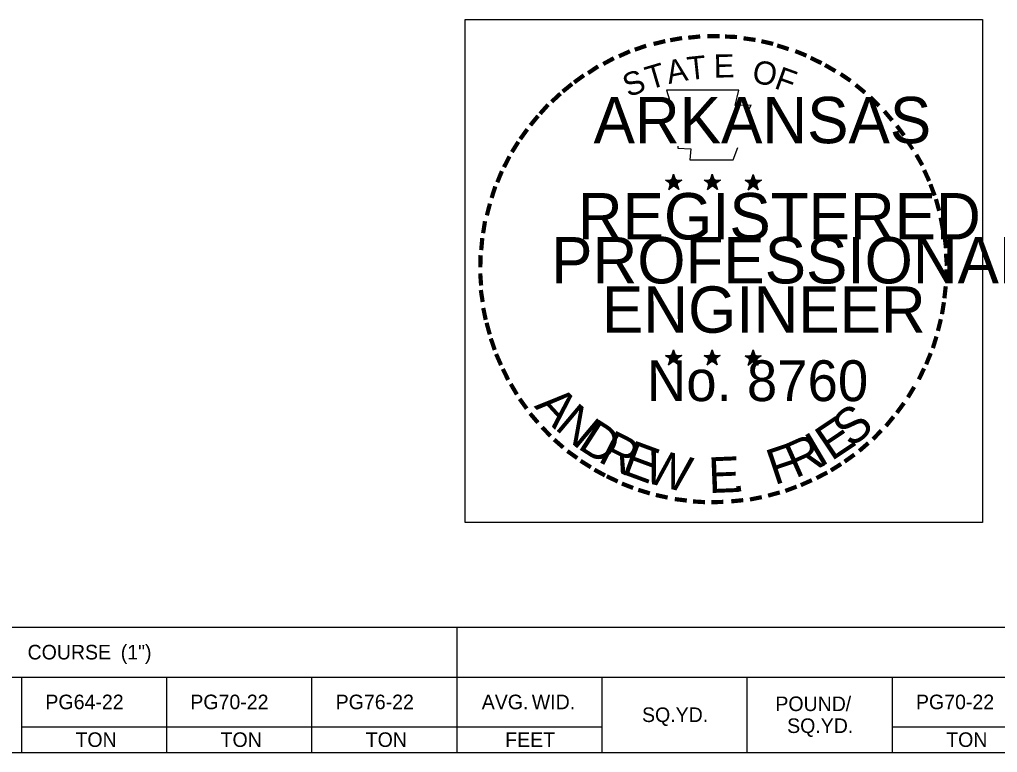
# Model space of a CAD drawing. Extents: x 1226590 to 1228573, y 151304 to 154224.
# Drawn here: x 1227484.8 to 1227748.5, y 152148.3 to 152345.9 of the extents above; entities that cross this region are included whole.
import ezdxf

# ---------------------------------------------------------------- set-up
doc = ezdxf.new("R2010")
doc.units = 0
for name, color, linetype in [('R_Border PE', 7, 'Continuous'), ('R_Border Prem', 7, 'Continuous'), ('R_Dimension', 7, 'Continuous')]:
    doc.layers.add(name, color=color, linetype=linetype)

msp = doc.modelspace()

# ---------------------------------------------------------------- linework, layer by layer
at = {"layer": 'R_Border PE'}
for p, q in [((1227661.2, 152304.28), (1227660.89, 152302.72)), ((1227661.2, 152304.28), (1227660.95, 152302.65)), ((1227661.2, 152304.28), (1227661.14, 152302.72)), ((1227661.2, 152301.97), (1227661.2, 152304.28)), ((1227661.2, 152304.28), (1227661.64, 152302.65)), ((1227661.2, 152304.28), (1227661.52, 152302.72)), ((1227661.2, 152304.28), (1227661.39, 152302.72)), ((1227671.64, 152304.28), (1227671.33, 152302.72)), ((1227671.64, 152304.28), (1227671.39, 152302.65)), ((1227671.64, 152304.28), (1227671.52, 152302.72)), ((1227671.64, 152301.97), (1227671.64, 152304.28)), ((1227671.64, 152304.28), (1227672.08, 152302.65)), ((1227671.64, 152304.28), (1227671.95, 152302.72)), ((1227671.64, 152304.28), (1227671.77, 152302.72)), ((1227659.02, 152302.65), (1227661.2, 152301.97)), ((1227659.02, 152302.65), (1227660.64, 152302.53)), ((1227659.02, 152302.65), (1227660.64, 152302.4)), ((1227659.02, 152302.65), (1227660.58, 152302.28)), ((1227659.02, 152302.65), (1227660.58, 152302.03)), ((1227659.02, 152302.65), (1227660.52, 152301.9)), ((1227659.02, 152302.65), (1227660.52, 152301.78)), ((1227659.89, 152300.09), (1227661.2, 152301.97)), ((1227659.89, 152300.09), (1227660.58, 152301.84)), ((1227659.89, 152300.09), (1227660.64, 152301.65)), ((1227659.89, 152300.09), (1227660.77, 152301.59)), ((1227663.39, 152302.65), (1227661.2, 152301.97)), ((1227662.58, 152300.09), (1227661.2, 152301.97)), ((1227663.39, 152302.65), (1227661.45, 152302.53)), ((1227663.39, 152302.65), (1227661.58, 152302.34)), ((1227663.39, 152302.65), (1227661.58, 152302.22)), ((1227662.58, 152300.09), (1227661.64, 152301.65)), ((1227662.58, 152300.09), (1227661.7, 152301.9)), ((1227662.58, 152300.09), (1227661.83, 152301.97)), ((1227663.39, 152302.65), (1227662.02, 152302.09)), ((1227663.39, 152302.65), (1227662.14, 152302.03)), ((1227663.39, 152302.65), (1227662.2, 152301.97)), ((1227669.45, 152302.65), (1227671.64, 152301.97)), ((1227669.45, 152302.65), (1227671.08, 152302.53)), ((1227669.45, 152302.65), (1227671.08, 152302.4)), ((1227669.45, 152302.65), (1227671.02, 152302.28)), ((1227669.45, 152302.65), (1227670.95, 152302.03)), ((1227669.45, 152302.65), (1227670.95, 152301.9)), ((1227669.45, 152302.65), (1227670.95, 152301.78)), ((1227670.33, 152300.09), (1227671.64, 152301.97)), ((1227670.33, 152300.09), (1227671.02, 152301.84)), ((1227670.33, 152300.09), (1227671.08, 152301.65)), ((1227670.33, 152300.09), (1227671.2, 152301.59)), ((1227673.83, 152302.65), (1227671.64, 152301.97)), ((1227673.02, 152300.09), (1227671.64, 152301.97)), ((1227673.83, 152302.65), (1227671.89, 152302.53)), ((1227673.83, 152302.65), (1227672.02, 152302.34)), ((1227673.83, 152302.65), (1227672.02, 152302.22)), ((1227673.02, 152300.09), (1227672.08, 152301.65)), ((1227673.02, 152300.09), (1227672.14, 152301.9)), ((1227673.02, 152300.09), (1227672.27, 152301.97)), ((1227673.83, 152302.65), (1227672.45, 152302.09)), ((1227673.83, 152302.65), (1227672.58, 152302.03)), ((1227673.83, 152302.65), (1227672.64, 152301.97)), ((1227680.52, 152302.59), (1227682.7, 152301.9)), ((1227680.52, 152302.59), (1227682.14, 152302.4)), ((1227680.52, 152302.59), (1227682.08, 152302.28)), ((1227680.52, 152302.59), (1227682.08, 152302.22)), ((1227680.52, 152302.59), (1227682.02, 152301.97)), ((1227680.52, 152302.59), (1227682.02, 152301.84)), ((1227680.52, 152302.59), (1227682.02, 152301.72)), ((1227681.33, 152300.03), (1227682.7, 152301.9)), ((1227681.33, 152300.03), (1227682.08, 152301.78)), ((1227681.33, 152300.03), (1227682.14, 152301.59)), ((1227681.33, 152300.03), (1227682.27, 152301.53)), ((1227682.7, 152304.15), (1227682.33, 152302.65)), ((1227682.7, 152304.15), (1227682.45, 152302.59)), ((1227682.7, 152304.15), (1227682.58, 152302.59)), ((1227682.7, 152301.9), (1227682.7, 152304.15)), ((1227682.7, 152304.15), (1227683.14, 152302.59)), ((1227682.7, 152304.15), (1227683.02, 152302.59)), ((1227682.7, 152304.15), (1227682.83, 152302.65)), ((1227684.89, 152302.59), (1227682.7, 152301.9)), ((1227684.02, 152300.03), (1227682.7, 152301.9)), ((1227684.89, 152302.59), (1227682.95, 152302.47)), ((1227684.89, 152302.59), (1227683.08, 152302.28)), ((1227684.89, 152302.59), (1227683.08, 152302.15)), ((1227684.02, 152300.03), (1227683.14, 152301.59)), ((1227684.02, 152300.03), (1227683.2, 152301.84)), ((1227684.02, 152300.03), (1227683.33, 152301.84)), ((1227684.89, 152302.59), (1227683.52, 152302.03)), ((1227684.89, 152302.59), (1227683.58, 152301.97)), ((1227684.89, 152302.59), (1227683.7, 152301.9)), ((1227659.89, 152300.09), (1227661.2, 152301.47)), ((1227659.89, 152300.09), (1227660.95, 152301.4)), ((1227659.89, 152300.09), (1227661.27, 152301.28)), ((1227662.58, 152300.09), (1227661.2, 152301.47)), ((1227662.58, 152300.09), (1227661.2, 152301.28)), ((1227662.58, 152300.09), (1227661.45, 152301.4)), ((1227670.33, 152300.09), (1227671.64, 152301.47)), ((1227670.33, 152300.09), (1227671.39, 152301.4)), ((1227670.33, 152300.09), (1227671.7, 152301.28)), ((1227673.02, 152300.09), (1227671.64, 152301.47)), ((1227673.02, 152300.09), (1227671.64, 152301.28)), ((1227673.02, 152300.09), (1227671.89, 152301.4)), ((1227681.33, 152300.03), (1227682.7, 152301.4)), ((1227681.33, 152300.03), (1227682.45, 152301.34)), ((1227681.33, 152300.03), (1227682.77, 152301.22)), ((1227684.02, 152300.03), (1227682.7, 152301.4)), ((1227684.02, 152300.03), (1227682.7, 152301.22)), ((1227684.02, 152300.03), (1227682.95, 152301.34)), ((1227661.2, 152256.9), (1227660.83, 152255.4)), ((1227661.2, 152256.9), (1227660.95, 152255.34)), ((1227661.2, 152256.9), (1227661.08, 152255.34)), ((1227661.2, 152254.65), (1227661.2, 152256.9)), ((1227661.2, 152256.9), (1227661.64, 152255.34)), ((1227661.2, 152256.9), (1227661.52, 152255.34)), ((1227661.2, 152256.9), (1227661.33, 152255.34)), ((1227671.64, 152256.9), (1227671.27, 152255.4)), ((1227671.64, 152256.9), (1227671.39, 152255.34)), ((1227671.64, 152256.9), (1227671.52, 152255.34)), ((1227671.64, 152254.65), (1227671.64, 152256.9)), ((1227671.64, 152256.9), (1227672.02, 152255.34)), ((1227671.64, 152256.9), (1227671.95, 152255.34)), ((1227671.64, 152256.9), (1227671.77, 152255.34)), ((1227682.7, 152256.84), (1227682.33, 152255.28)), ((1227682.7, 152256.84), (1227682.45, 152255.28)), ((1227682.7, 152256.84), (1227682.58, 152255.28)), ((1227682.7, 152254.59), (1227682.7, 152256.84)), ((1227682.7, 152256.84), (1227683.08, 152255.28)), ((1227682.7, 152256.84), (1227683.02, 152255.28)), ((1227682.7, 152256.84), (1227682.83, 152255.28)), ((1227659.02, 152255.34), (1227661.2, 152254.65)), ((1227659.02, 152255.34), (1227660.64, 152255.15)), ((1227659.02, 152255.34), (1227660.58, 152255.03)), ((1227659.02, 152255.34), (1227660.58, 152254.97)), ((1227659.02, 152255.34), (1227660.52, 152254.72)), ((1227659.02, 152255.34), (1227660.52, 152254.59)), ((1227659.02, 152255.34), (1227660.52, 152254.47)), ((1227659.83, 152252.78), (1227661.2, 152254.65)), ((1227659.83, 152252.78), (1227660.58, 152254.53)), ((1227659.83, 152252.78), (1227660.64, 152254.28)), ((1227659.83, 152252.78), (1227660.77, 152254.22)), ((1227659.83, 152252.78), (1227661.2, 152254.15)), ((1227659.83, 152252.78), (1227660.95, 152254.09)), ((1227663.39, 152255.34), (1227661.2, 152254.65)), ((1227662.52, 152252.78), (1227661.2, 152254.65)), ((1227662.52, 152252.78), (1227661.2, 152254.09)), ((1227662.52, 152252.78), (1227661.39, 152254.09)), ((1227663.39, 152255.34), (1227661.45, 152255.22)), ((1227663.39, 152255.34), (1227661.58, 152255.03)), ((1227663.39, 152255.34), (1227661.58, 152254.9)), ((1227662.52, 152252.78), (1227661.64, 152254.59)), ((1227662.52, 152252.78), (1227661.64, 152254.34)), ((1227662.52, 152252.78), (1227661.83, 152254.59)), ((1227663.39, 152255.34), (1227661.95, 152254.78)), ((1227663.39, 152255.34), (1227662.08, 152254.72)), ((1227663.39, 152255.34), (1227662.2, 152254.59)), ((1227669.45, 152255.34), (1227671.64, 152254.65)), ((1227669.45, 152255.34), (1227671.02, 152255.15)), ((1227669.45, 152255.34), (1227671.02, 152255.03)), ((1227669.45, 152255.34), (1227671.02, 152254.97)), ((1227669.45, 152255.34), (1227670.95, 152254.72)), ((1227669.45, 152255.34), (1227670.95, 152254.59)), ((1227669.45, 152255.34), (1227670.95, 152254.47)), ((1227670.27, 152252.78), (1227671.64, 152254.65)), ((1227670.27, 152252.78), (1227671.02, 152254.53)), ((1227670.27, 152252.78), (1227671.08, 152254.28)), ((1227670.27, 152252.78), (1227671.2, 152254.22)), ((1227670.27, 152252.78), (1227671.64, 152254.15)), ((1227670.27, 152252.78), (1227671.39, 152254.09)), ((1227673.77, 152255.34), (1227671.64, 152254.65)), ((1227672.95, 152252.78), (1227671.64, 152254.65)), ((1227672.95, 152252.78), (1227671.64, 152254.09)), ((1227672.95, 152252.78), (1227671.83, 152254.09)), ((1227673.77, 152255.34), (1227671.89, 152255.22)), ((1227673.77, 152255.34), (1227672.02, 152255.03)), ((1227673.77, 152255.34), (1227672.02, 152254.9)), ((1227672.95, 152252.78), (1227672.08, 152254.59)), ((1227672.95, 152252.78), (1227672.08, 152254.34)), ((1227672.95, 152252.78), (1227672.27, 152254.59)), ((1227673.77, 152255.34), (1227672.39, 152254.78)), ((1227673.77, 152255.34), (1227672.52, 152254.72)), ((1227673.77, 152255.34), (1227672.64, 152254.59)), ((1227680.52, 152255.28), (1227682.7, 152254.59)), ((1227680.52, 152255.28), (1227682.08, 152255.09)), ((1227680.52, 152255.28), (1227682.08, 152254.97)), ((1227680.52, 152255.28), (1227682.02, 152254.84)), ((1227680.52, 152255.28), (1227682.02, 152254.65)), ((1227680.52, 152255.28), (1227681.95, 152254.47)), ((1227680.52, 152255.28), (1227681.95, 152254.34)), ((1227681.33, 152252.72), (1227682.7, 152254.59)), ((1227681.33, 152252.72), (1227682.02, 152254.47)), ((1227681.33, 152252.72), (1227682.08, 152254.22)), ((1227681.33, 152252.72), (1227682.27, 152254.15)), ((1227684.83, 152255.28), (1227682.7, 152254.59)), ((1227684.02, 152252.72), (1227682.7, 152254.59)), ((1227684.83, 152255.28), (1227682.95, 152255.15)), ((1227684.83, 152255.28), (1227683.08, 152254.97)), ((1227684.83, 152255.28), (1227683.08, 152254.84)), ((1227684.02, 152252.72), (1227683.08, 152254.22)), ((1227684.02, 152252.72), (1227683.14, 152254.53)), ((1227684.02, 152252.72), (1227683.27, 152254.53)), ((1227684.83, 152255.28), (1227683.45, 152254.72)), ((1227684.83, 152255.28), (1227683.58, 152254.59)), ((1227684.83, 152255.28), (1227683.64, 152254.53)), ((1227659.83, 152252.78), (1227661.2, 152253.97)), ((1227662.52, 152252.78), (1227661.14, 152253.97)), ((1227670.27, 152252.78), (1227671.64, 152253.97)), ((1227672.95, 152252.78), (1227671.58, 152253.97)), ((1227681.33, 152252.72), (1227682.45, 152254.03)), ((1227681.33, 152252.72), (1227682.64, 152254.03)), ((1227681.33, 152252.72), (1227682.7, 152253.9)), ((1227684.02, 152252.72), (1227682.64, 152254.03)), ((1227684.02, 152252.72), (1227682.64, 152253.84)), ((1227684.02, 152252.72), (1227682.89, 152254.03))]:
    msp.add_line(p, q, dxfattribs=at)
for points in [[(1227659.33, 152326.9), (1227660.95, 152321.72)], [(1227681.27, 152321.15), (1227682.14, 152322.9), (1227677.83, 152322.78), (1227678.77, 152326.9), (1227659.33, 152326.9)], [(1227662.39, 152311.78), (1227662.39, 152311.22), (1227665.89, 152311.09), (1227665.58, 152308.15), (1227677.27, 152308.15), (1227678.52, 152311.47)], [(1227661.2, 152304.28), (1227662.58, 152300.09), (1227659.02, 152302.65), (1227663.39, 152302.65), (1227659.89, 152300.09), (1227661.2, 152304.28)], [(1227671.64, 152304.28), (1227673.02, 152300.09), (1227669.45, 152302.65), (1227673.83, 152302.65), (1227670.33, 152300.09), (1227671.64, 152304.28)], [(1227682.7, 152304.15), (1227684.02, 152300.03), (1227680.52, 152302.59), (1227684.89, 152302.59), (1227681.33, 152300.03), (1227682.7, 152304.15)], [(1227661.2, 152256.9), (1227662.52, 152252.78), (1227659.02, 152255.34), (1227663.39, 152255.34), (1227659.83, 152252.78), (1227661.2, 152256.9)], [(1227671.64, 152256.9), (1227672.95, 152252.78), (1227669.45, 152255.34), (1227673.77, 152255.34), (1227670.27, 152252.78), (1227671.64, 152256.9)], [(1227682.7, 152256.84), (1227684.02, 152252.72), (1227680.52, 152255.28), (1227684.83, 152255.28), (1227681.33, 152252.72), (1227682.7, 152256.84)]]:
    msp.add_lwpolyline(points, dxfattribs=at)
for centre, radius in [((1227661.22, 152301.96), 1.08), ((1227661.22, 152301.96), 0.975), ((1227661.22, 152301.96), 0.904), ((1227661.22, 152301.96), 0.83), ((1227661.22, 152301.96), 0.723), ((1227661.22, 152301.96), 0.672), ((1227661.22, 152301.96), 0.619), ((1227661.22, 152301.96), 0.533), ((1227661.22, 152301.96), 0.467), ((1227661.22, 152301.96), 0.388), ((1227661.22, 152301.96), 0.31), ((1227661.22, 152301.96), 0.231), ((1227661.22, 152301.96), 0.185), ((1227661.22, 152301.96), 0.0901), ((1227671.65, 152301.96), 1.08), ((1227671.65, 152301.96), 0.975), ((1227671.65, 152301.96), 0.904), ((1227671.65, 152301.96), 0.83), ((1227671.65, 152301.96), 0.723), ((1227671.65, 152301.96), 0.672), ((1227671.65, 152301.96), 0.619), ((1227671.65, 152301.96), 0.533), ((1227671.65, 152301.96), 0.467), ((1227671.65, 152301.96), 0.388), ((1227671.65, 152301.96), 0.31), ((1227671.65, 152301.96), 0.231), ((1227671.65, 152301.96), 0.185), ((1227671.65, 152301.96), 0.0901), ((1227682.7, 152301.89), 1.08), ((1227682.7, 152301.89), 0.975), ((1227682.7, 152301.89), 0.904), ((1227682.7, 152301.89), 0.83), ((1227682.7, 152301.89), 0.723), ((1227682.7, 152301.89), 0.672), ((1227682.7, 152301.89), 0.619), ((1227682.7, 152301.89), 0.533), ((1227682.7, 152301.89), 0.467), ((1227682.7, 152301.89), 0.388), ((1227682.7, 152301.89), 0.31), ((1227682.7, 152301.89), 0.231), ((1227682.7, 152301.89), 0.185), ((1227682.7, 152301.89), 0.0901), ((1227661.2, 152254.63), 1.08), ((1227661.2, 152254.63), 0.975), ((1227661.2, 152254.63), 0.904), ((1227661.2, 152254.63), 0.83), ((1227661.2, 152254.63), 0.723), ((1227661.2, 152254.63), 0.672), ((1227661.2, 152254.63), 0.619), ((1227661.2, 152254.63), 0.533), ((1227661.2, 152254.63), 0.467), ((1227661.2, 152254.63), 0.388), ((1227661.2, 152254.63), 0.31), ((1227661.2, 152254.63), 0.231), ((1227661.2, 152254.63), 0.185), ((1227661.2, 152254.63), 0.0901), ((1227671.63, 152254.63), 1.08), ((1227671.63, 152254.63), 0.975), ((1227671.63, 152254.63), 0.904), ((1227671.63, 152254.63), 0.83), ((1227671.63, 152254.63), 0.723), ((1227671.63, 152254.63), 0.672), ((1227671.63, 152254.63), 0.619), ((1227671.63, 152254.63), 0.533), ((1227671.63, 152254.63), 0.467), ((1227671.63, 152254.63), 0.388), ((1227671.63, 152254.63), 0.31), ((1227671.63, 152254.63), 0.231), ((1227671.63, 152254.63), 0.185), ((1227671.63, 152254.63), 0.0901), ((1227682.67, 152254.56), 1.08), ((1227682.67, 152254.56), 0.975), ((1227682.67, 152254.56), 0.904), ((1227682.67, 152254.56), 0.83), ((1227682.67, 152254.56), 0.723), ((1227682.67, 152254.56), 0.672), ((1227682.67, 152254.56), 0.619), ((1227682.67, 152254.56), 0.533), ((1227682.67, 152254.56), 0.467), ((1227682.67, 152254.56), 0.388), ((1227682.67, 152254.56), 0.31), ((1227682.67, 152254.56), 0.231), ((1227682.67, 152254.56), 0.185), ((1227682.67, 152254.56), 0.0901)]:
    msp.add_circle(centre, radius, dxfattribs=at)
at = {"layer": 'R_Border Prem'}
msp.add_lwpolyline([(1227604.98, 152345.95), (1227744.48, 152345.95), (1227744.48, 152210.33), (1227604.98, 152210.33)], close=True, dxfattribs=at)
at = {"layer": 'R_Dimension'}
for p, q in [((1226590.27, 152182.03), (1228150.73, 152182.03)), ((1227602.82, 152148.27), (1227602.82, 152182.03)), ((1226898.37, 152168.6), (1228150.73, 152168.6)), ((1227485.41, 152148.27), (1227485.41, 152168.6)), ((1227524.55, 152148.27), (1227524.55, 152168.6)), ((1227563.69, 152148.27), (1227563.69, 152168.6)), ((1227641.96, 152148.27), (1227641.96, 152168.6)), ((1227681.09, 152148.27), (1227681.09, 152168.6)), ((1227720.23, 152148.27), (1227720.23, 152168.6)), ((1227485.41, 152155.17), (1227641.96, 152155.17)), ((1227720.23, 152155.17), (1227837.64, 152155.17)), ((1226590.27, 152148.27), (1228150.73, 152148.27)), ((1227407.14, 152148.27), (1227641.96, 152148.27)), ((1227641.96, 152148.27), (1227876.78, 152148.27))]:
    msp.add_line(p, q, dxfattribs=at)

# ---------------------------------------------------------------- texts
at = {"layer": 'R_Border PE'}
for s, height, rotation, p in [('-', 10, 10.2193, (1227660.39, 152336.47)), ('-', 10, 5.8968, (1227664.95, 152337.15)), ('-', 10, 0.1862, (1227669.77, 152337.59)), ('-', 10, 357.743, (1227674.33, 152337.53)), ('-', 10, 352.1617, (1227678.95, 152337.15)), ('-', 10, 19.1761, (1227651.45, 152333.97)), ('-', 10, 13.6302, (1227656.14, 152335.47)), ('-', 10, 347.2049, (1227683.45, 152336.47)), ('-', 10, 342.3362, (1227687.39, 152335.47)), ('-', 10, 28.7918, (1227643.58, 152330.28)), ('-', 10, 24.3072, (1227647.52, 152332.28)), ('T', 6.25, 6.0228, (1227665.2, 152329.59)), ('E', 6.25, 0.8323, (1227672.08, 152330.28)), ('-', 10, 337.8551, (1227692.02, 152334.09)), ('-', 10, 334.1211, (1227695.95, 152332.4)), ('-', 10, 34.0636, (1227639.83, 152327.97)), ('T', 6.25, 16.4036, (1227654.7, 152326.97)), ('A', 6.25, 11.2132, (1227659.89, 152328.53)), ('O', 6.25, 350.4515, (1227682.14, 152328.97)), ('-', 10, 329.6409, (1227699.58, 152330.65)), ('-', 10, 36.2317, (1227636.2, 152325.53)), ('S', 6.25, 21.594, (1227649.02, 152324.9)), ('F', 6.25, 340.0707, (1227688.08, 152327.53)), ('-', 10, 325.8627, (1227703.58, 152328.4)), ('-', 10, 38.9507, (1227633.27, 152323.15)), ('-', 10, 320.5297, (1227707.39, 152325.72)), ('-', 10, 42.9622, (1227630.52, 152320.53)), ('-', 10, 315.5786, (1227711.14, 152322.65)), ('-', 10, 48.423, (1227627.7, 152317.53)), ('-', 10, 50.6142, (1227625.2, 152314.53)), ('-', 10, 309.8797, (1227714.7, 152319.22)), ('-', 10, 306.6522, (1227717.95, 152315.47)), ('-', 10, 54.2325, (1227622.64, 152310.97)), ('-', 10, 58.0706, (1227620.58, 152307.65)), ('-', 8.75, 303.6753, (1227721.02, 152311.9)), ('-', 10, 299.6684, (1227723.02, 152308.09)), ('-', 10, 62.8713, (1227618.64, 152303.84)), ('-', 10, 67.7743, (1227617.02, 152300.03)), ('-', 10, 294.6628, (1227725.02, 152304.28)), ('-', 10, 290.5728, (1227726.64, 152300.72)), ('-', 10, 72.3945, (1227615.64, 152296.09)), ('-', 10, 75.461, (1227614.45, 152291.59)), ('-', 10, 285.1233, (1227728.08, 152297.09)), ('-', 10, 81.2013, (1227613.58, 152287.15)), ('-', 10, 280.5493, (1227729.33, 152292.4)), ('-', 10, 85.1863, (1227613.14, 152282.84)), ('-', 10, 276.5962, (1227730.39, 152287.65)), ('-', 10, 89.0622, (1227612.95, 152278.47)), ('-', 10, 274.3301, (1227730.77, 152283.09)), ('-', 10, 269.9407, (1227730.95, 152279.15)), ('-', 10, 94.1959, (1227613.2, 152273.9)), ('-', 10, 98.9479, (1227613.64, 152269.78)), ('-', 10, 263.5172, (1227730.83, 152275.03)), ('-', 10, 101.7149, (1227614.45, 152265.15)), ('-', 10, 260.9953, (1227730.39, 152270.9)), ('-', 10, 255.7626, (1227729.7, 152266.65)), ('-', 10, 105.4578, (1227615.52, 152261.47)), ('-', 10, 109.0874, (1227616.83, 152257.53)), ('-', 10, 252.8681, (1227728.58, 152262.15)), ('-', 10, 114.0643, (1227618.45, 152253.78)), ('-', 10, 247.8887, (1227727.2, 152257.97)), ('-', 10, 115.7289, (1227620.33, 152249.9)), ('-', 10, 244.6197, (1227725.52, 152254.03)), ('-', 10, 120.4471, (1227622.58, 152246.28)), ('-', 10, 239.0712, (1227723.08, 152249.34)), ('-', 10, 125.8934, (1227625.08, 152242.78)), ('A', 9.62, 312.4727, (1227623.45, 152241.58)), ('N', 9.62, 319.8362, (1227628.89, 152235.65)), ('S', 9.62, 39.723, (1227709.12, 152230.19)), ('-', 10, 233.8452, (1227720.58, 152245.28)), ('-', 10, 130.7181, (1227627.95, 152239.28)), ('E', 9.62, 33.8878, (1227703.78, 152226.7)), ('-', 10, 231.2538, (1227717.89, 152241.72)), ('-', 10, 134.2238, (1227631.2, 152235.9)), ('D', 9.62, 327.1996, (1227635.03, 152230.46)), ('-', 10, 138.9338, (1227634.45, 152233.03)), ('R', 9.62, 333.1738, (1227640.48, 152226.86)), ('R', 9.62, 24.0235, (1227694.04, 152222.1)), ('I', 9.62, 30.5534, (1227700.58, 152224.96)), ('-', 10, 225.7653, (1227714.89, 152238.22)), ('E', 9.62, 339.7037, (1227646.82, 152223.6)), ('W', 9.62, 345.5389, (1227652.77, 152221.31)), ('F', 9.62, 18.6051, (1227688.4, 152220.31)), ('-', 10, 221.0851, (1227711.64, 152235.03)), ('-', 10, 144.6463, (1227637.95, 152230.47)), ('E', 9.62, 2.2804, (1227670.74, 152218.21)), ('-', 10, 215.7363, (1227708.2, 152232.09)), ('-', 10, 148.0898, (1227641.45, 152228.15)), ('-', 10, 212.2491, (1227704.83, 152229.65)), ('-', 10, 151.5704, (1227645.08, 152226.09)), ('-', 10, 154.6002, (1227648.33, 152224.59)), ('-', 10, 207.3568, (1227701.39, 152227.47)), ('-', 10, 158.5612, (1227652.27, 152222.97)), ('.', 9.62, 8.1156, (1227677.11, 152218.38)), ('-', 10, 200.7184, (1227693.58, 152223.78)), ('-', 10, 204.2516, (1227697.45, 152225.47)), ('-', 10, 162.7983, (1227656.52, 152221.65)), ('-', 10, 167.5555, (1227661.02, 152220.65)), ('-', 10, 173.1155, (1227665.83, 152219.97)), ('-', 10, 191.2858, (1227684.83, 152221.03)), ('-', 10, 195.4743, (1227689.39, 152222.28)), ('-', 10, 176.5183, (1227670.52, 152219.59)), ('-', 10, 181.5918, (1227675.14, 152219.72)), ('-', 10, 185.8167, (1227680.2, 152220.22))]:
    msp.add_text(s, height=height, rotation=rotation, dxfattribs=at).set_placement(p)
for s, height, p in [('ARKANSAS', 12.5, (1227639.64, 152312.59)), ('REGISTERED', 12.5, (1227635.39, 152286.65)), ('PROFESSIONAL', 12.4999, (1227628.2, 152274.78)), ('ENGINEER', 12.5, (1227641.89, 152261.47)), ('No. 8760', 11, (1227654, 152243.03))]:
    msp.add_text(s, height=height, dxfattribs=at).set_placement(p)
at = {"layer": 'R_Dimension'}
for s, p in [(' COURSE', (1227485.54, 152173.35)), (' (1")', (1227510.67, 152173.35)), ('PG', (1227491.81, 152159.92)), (' 64-22', (1227497.98, 152159.92)), ('PG', (1227530.89, 152159.92)), (' 70-22', (1227537.05, 152159.92)), ('PG', (1227570.08, 152159.92)), (' 76-22', (1227576.25, 152159.92)), ('AVG.', (1227609.48, 152159.92)), (' WID.', (1227621.51, 152159.92)), ('POUND', (1227688.66, 152159.42)), (' /', (1227706.16, 152159.42)), ('PG', (1227726.57, 152159.92)), (' 70-22', (1227732.73, 152159.92)), ('SQ.YD.', (1227652.7, 152156.47)), ('SQ.YD.', (1227691.83, 152153.51)), ('TON', (1227499.92, 152149.75)), ('TON', (1227539.05, 152149.75)), ('TON', (1227578.19, 152149.75)), ('FEET', (1227615.81, 152149.75)), ('TON', (1227734.73, 152149.75))]:
    msp.add_text(s, height=3.935, dxfattribs=at).set_placement(p)

doc.saveas('drawing.dxf')
